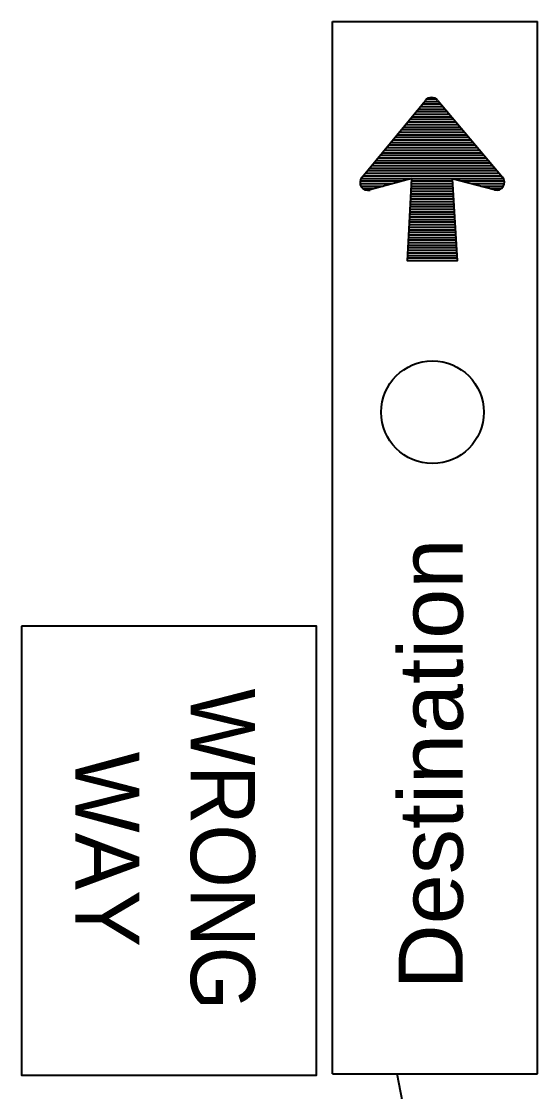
# Model space of a CAD drawing. Extents: x -133 to 547, y -328 to 112.
# Drawn here: x 171.56 to 190.88, y 2.33 to 42.36 of the extents above; entities that cross this region are included whole.
import ezdxf
from ezdxf.enums import TextEntityAlignment as Align

# ---------------------------------------------------------------- set-up
doc = ezdxf.new("R2010")
doc.units = 0
doc.header["$LTSCALE"] = 0.8
doc.layers.add('1', color=7, linetype='Continuous', lineweight=35)

msp = doc.modelspace()

# ---------------------------------------------------------------- linework, layer by layer
at = {"layer": '1', "lineweight": 40}
for p, q in [((183.2001, 2.9964), (183.2001, 42.3564)), ((183.2001, 42.3564), (190.8801, 42.3564)), ((190.8801, 2.9964), (190.8801, 42.3564)), ((187.2657, 39.2572), (186.5649, 39.2572)), ((186.9585, 39.2572), (186.5649, 39.2572)), ((187.1889, 39.3532), (186.6417, 39.3532)), ((186.9585, 39.3532), (186.6417, 39.3532)), ((187.5921, 38.8732), (186.2481, 38.8732)), ((186.9585, 38.8732), (186.2481, 38.8732)), ((187.5152, 38.9692), (186.3249, 38.9692)), ((186.9585, 38.9692), (186.3249, 38.9692)), ((187.4289, 39.0652), (186.4112, 39.0652)), ((186.9585, 39.0652), (186.4112, 39.0652)), ((187.3521, 39.1612), (186.4881, 39.1612)), ((186.9585, 39.1612), (186.4881, 39.1612)), ((187.9089, 38.4892), (185.9313, 38.4892)), ((186.9585, 38.4892), (185.9313, 38.4892)), ((187.8225, 38.5852), (186.0081, 38.5852)), ((186.9585, 38.5852), (186.0081, 38.5852)), ((187.7457, 38.6812), (186.0849, 38.6812)), ((186.9585, 38.6812), (186.0849, 38.6812)), ((187.6689, 38.7772), (186.1712, 38.7772)), ((186.9585, 38.7772), (186.1712, 38.7772)), ((188.2353, 38.1052), (185.6145, 38.1052)), ((186.9585, 38.1052), (185.6145, 38.1052)), ((188.1489, 38.2012), (185.6912, 38.2012)), ((186.9585, 38.2012), (185.6912, 38.2012)), ((188.0721, 38.2972), (185.7681, 38.2972)), ((186.9585, 38.2972), (185.7681, 38.2972)), ((187.9857, 38.3932), (185.8545, 38.3932)), ((186.9585, 38.3932), (185.8545, 38.3932)), ((188.5617, 37.7212), (185.2977, 37.7212)), ((186.9585, 37.7212), (185.2977, 37.7212)), ((188.4752, 37.8172), (185.3745, 37.8172)), ((186.9585, 37.8172), (185.3745, 37.8172)), ((188.3985, 37.9132), (185.4512, 37.9132)), ((186.9585, 37.9132), (185.4512, 37.9132)), ((188.3121, 38.0092), (185.5377, 38.0092)), ((186.9585, 38.0092), (185.5377, 38.0092)), ((188.9649, 37.2413), (184.8945, 37.2413)), ((186.9585, 37.2413), (184.8945, 37.2413)), ((188.8785, 37.3372), (184.9809, 37.3372)), ((186.9585, 37.3372), (184.9809, 37.3372)), ((188.8017, 37.4332), (185.0577, 37.4332)), ((186.9585, 37.4332), (185.0577, 37.4332)), ((188.7249, 37.5292), (185.1345, 37.5292)), ((186.9585, 37.5292), (185.1345, 37.5292)), ((188.6385, 37.6252), (185.2209, 37.6252)), ((186.9585, 37.6252), (185.2209, 37.6252)), ((189.2912, 36.8573), (184.5777, 36.8573)), ((186.9585, 36.8573), (184.5777, 36.8573)), ((189.2049, 36.9532), (184.6641, 36.9532)), ((186.9585, 36.9532), (184.6641, 36.9532)), ((189.1281, 37.0493), (184.7409, 37.0493)), ((186.9585, 37.0493), (184.7409, 37.0493)), ((189.0417, 37.1452), (184.8177, 37.1452)), ((186.9585, 37.1452), (184.8177, 37.1452)), ((189.5312, 36.5692), (184.3473, 36.5692)), ((186.9585, 36.5692), (184.3473, 36.5692)), ((189.4545, 36.6653), (184.4241, 36.6653)), ((186.9585, 36.6653), (184.4241, 36.6653)), ((189.3681, 36.7612), (184.5009, 36.7612)), ((186.9585, 36.7612), (184.5009, 36.7612)), ((186.9585, 36.4733), (186.1712, 36.4733)), ((185.7969, 36.3772), (184.2417, 36.3772)), ((185.7969, 36.3772), (184.2417, 36.3772)), ((185.4417, 36.2812), (184.2417, 36.2812)), ((185.4417, 36.2812), (184.2417, 36.2812)), ((187.7072, 36.0892), (186.1521, 36.0892)), ((186.9585, 36.0892), (186.1521, 36.0892)), ((187.6977, 36.2812), (186.1617, 36.2812)), ((186.9585, 36.2812), (186.1617, 36.2812)), ((187.6977, 36.1852), (186.1617, 36.1852)), ((186.9585, 36.1852), (186.1617, 36.1852)), ((187.6881, 36.3772), (186.1712, 36.3772)), ((186.9585, 36.3772), (186.1712, 36.3772)), ((189.6369, 36.3772), (188.0337, 36.3772)), ((189.5985, 36.1852), (188.7537, 36.1852)), ((187.7265, 35.7052), (186.1329, 35.7052)), ((186.9585, 35.7052), (186.1329, 35.7052)), ((187.7169, 35.8972), (186.1425, 35.8972)), ((186.9585, 35.8972), (186.1425, 35.8972)), ((187.7265, 35.8012), (186.1425, 35.8012)), ((186.9585, 35.8012), (186.1425, 35.8012)), ((187.7169, 35.9932), (186.1521, 35.9932)), ((186.9585, 35.9932), (186.1521, 35.9932)), ((187.7457, 35.3212), (186.1137, 35.3212)), ((186.9585, 35.3212), (186.1137, 35.3212)), ((187.7457, 35.5132), (186.1232, 35.5132)), ((186.9585, 35.5132), (186.1232, 35.5132)), ((187.7457, 35.4172), (186.1232, 35.4172)), ((186.9585, 35.4172), (186.1232, 35.4172)), ((187.7361, 35.6092), (186.1329, 35.6092)), ((186.9585, 35.6092), (186.1329, 35.6092)), ((187.7745, 34.8413), (186.0849, 34.8413)), ((186.9585, 34.8413), (186.0849, 34.8413)), ((187.7745, 34.9372), (186.0945, 34.9372)), ((186.9585, 34.9372), (186.0945, 34.9372)), ((187.7552, 35.1292), (186.1041, 35.1292)), ((186.9585, 35.1292), (186.1041, 35.1292)), ((187.7649, 35.0332), (186.1041, 35.0332)), ((186.9585, 35.0332), (186.1041, 35.0332)), ((187.7552, 35.2252), (186.1137, 35.2252)), ((186.9585, 35.2252), (186.1137, 35.2252)), ((187.8032, 34.4573), (186.0657, 34.4573)), ((186.9585, 34.4573), (186.0657, 34.4573)), ((187.7841, 34.6493), (186.0752, 34.6493)), ((186.9585, 34.6493), (186.0752, 34.6493)), ((187.7937, 34.5532), (186.0752, 34.5532)), ((186.9585, 34.5532), (186.0752, 34.5532)), ((187.7841, 34.7452), (186.0849, 34.7452)), ((186.9585, 34.7452), (186.0849, 34.7452)), ((187.8225, 34.0733), (186.0465, 34.0733)), ((186.9585, 34.0733), (186.0465, 34.0733)), ((187.8129, 34.2653), (186.0561, 34.2653)), ((186.9585, 34.2653), (186.0561, 34.2653)), ((187.8225, 34.1692), (186.0561, 34.1692)), ((186.9585, 34.1692), (186.0561, 34.1692)), ((187.8032, 34.3612), (186.0657, 34.3612)), ((186.9585, 34.3612), (186.0657, 34.3612)), ((187.8512, 33.6893), (186.0272, 33.6893)), ((186.9585, 33.6893), (186.0272, 33.6893)), ((187.8321, 33.8813), (186.0369, 33.8813)), ((186.9585, 33.8813), (186.0369, 33.8813)), ((187.8417, 33.7852), (186.0369, 33.7852)), ((186.9585, 33.7852), (186.0369, 33.7852)), ((187.8321, 33.9772), (186.0465, 33.9772)), ((186.9585, 33.9772), (186.0465, 33.9772)), ((187.8705, 33.4012), (186.0081, 33.4012)), ((186.9585, 33.4012), (186.0081, 33.4012)), ((187.8609, 33.4973), (186.0177, 33.4973)), ((186.9585, 33.4973), (186.0177, 33.4973)), ((187.8512, 33.5932), (186.0272, 33.5932)), ((186.9585, 33.5932), (186.0272, 33.5932)), ((183.2001, 2.9964), (190.8801, 2.9964))]:
    msp.add_line(p, q, dxfattribs=at)
at = {"layer": '1'}
for p, q in [((184.2993, 36.5213), (186.6801, 39.4012)), ((187.1409, 39.4012), (189.5697, 36.5308))]:
    msp.add_line(p, q, dxfattribs=at)
at = {"layer": '1', "lineweight": 40}
for points in [[(186.9585, 39.4492), (186.7472, 39.4492), (186.7377, 39.4492)], [(187.0832, 39.4492), (187.1025, 39.4492), (187.0832, 39.4492), (186.7472, 39.4492), (186.7472, 39.4492)], [(186.1425, 36.4733), (184.2801, 36.4733), (184.2705, 36.4733)], [(186.1425, 36.4733), (184.2801, 36.4733), (184.2705, 36.4733)], [(189.6081, 36.4733), (189.5985, 36.4733), (187.6785, 36.4733), (186.1712, 36.4733)], [(185.0961, 36.1852), (184.2801, 36.1852), (184.2705, 36.1852)], [(185.0961, 36.1852), (184.2801, 36.1852), (184.2705, 36.1852)], [(184.7505, 36.0892), (184.3665, 36.0892), (184.3569, 36.0892)], [(184.7505, 36.0892), (184.3665, 36.0892), (184.3569, 36.0892)], [(189.6369, 36.2812), (189.6273, 36.2812), (188.3985, 36.2812)], [(189.5121, 36.0892), (189.5025, 36.0892), (189.1089, 36.0892)]]:
    msp.add_lwpolyline(points, dxfattribs=at)
at = {"layer": '1'}
for points in [[(189.2625, 36.0508), (187.6785, 36.4733), (187.8705, 33.4012), (186.0081, 33.4012), (186.1712, 36.4828), (184.6065, 36.0508)], [(184.6337, -13.4898), (188.804, -13.4898), (185.6235, 2.9964)]]:
    msp.add_lwpolyline(points, dxfattribs=at)
at = {"layer": '1', "lineweight": 40}
msp.add_lwpolyline([(171.5601, 19.7364), (171.5601, 2.9364), (182.6001, 2.9364), (182.6001, 19.7364)], close=True, dxfattribs=at)
msp.add_circle((186.9446, 27.7376), 1.92, dxfattribs=at)
at = {"layer": '1'}
for centre, start, end in [((186.9103, 39.211), 40.25653, 140.40471), ((184.5302, 36.335), 140.43005, 285.55122), ((189.3436, 36.3385), 255.11373, 40.25762)]:
    msp.add_arc(centre, 0.2976, start, end, dxfattribs=at)

# ---------------------------------------------------------------- texts
for s, rotation, width, p in [('Destination', 90, 1.05, (188.0801, 14.5808)), ('WRONG', 270, 0.95, (177.9001, 11.3903))]:
    msp.add_text(s, height=2.4, rotation=rotation, dxfattribs=dict(at, width=width)).set_placement(p, align=Align.CENTER)
msp.add_text('WAY', height=2.4, rotation=270, dxfattribs=at).set_placement((173.5801, 11.3848), align=Align.CENTER)

doc.saveas('drawing.dxf')
